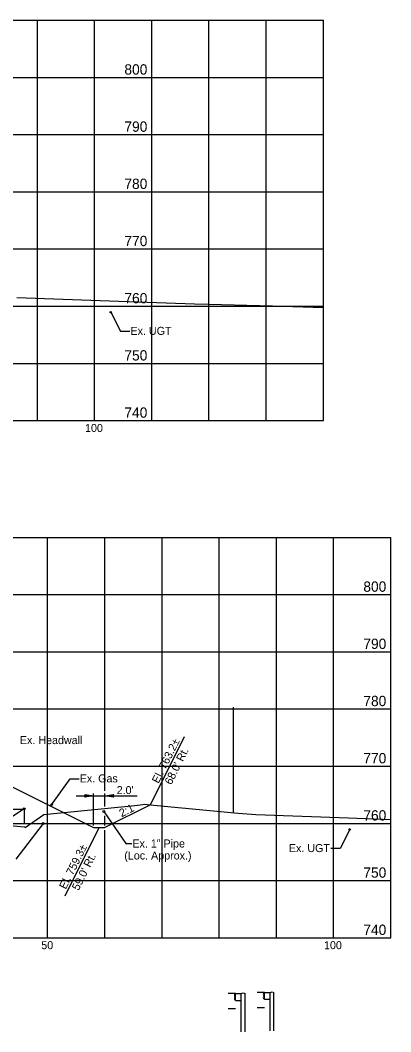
# Model space of a CAD drawing. Extents: x -1395 to 1843, y -1176 to 1887.
# Drawn here: x -168.7 to -39.1, y -802 to -448.3 of the extents above; entities that cross this region are included whole.
import ezdxf

# ---------------------------------------------------------------- set-up
doc = ezdxf.new("R2010")
doc.units = 0
for name, color, linetype in [('DR_X_Storm_Sewer', 7, 'Continuous'), ('GE_X_Alignment', 7, 'Continuous'), ('HY_X_Water_Edge', 7, 'Continuous'), ('PV_X_Shoulder', 7, 'Continuous'), ('RD_X_GR_Lt', 7, 'Continuous'), ('RW_P_Esmt_SH', 7, 'Continuous'), ('RW_P_Esmt_TMP', 7, 'Continuous'), ('RW_X_CL', 7, 'Continuous'), ('SH_Data', 7, 'Continuous'), ('SV_X_Break_Lines', 7, 'Continuous'), ('SV_X_Random_Point', 7, 'Continuous'), ('SV_X_Shot_Marker', 7, 'Continuous'), ('SV_X_Text_Name', 7, 'Continuous')]:
    doc.layers.add(name, color=color, linetype=linetype)

msp = doc.modelspace()

# ---------------------------------------------------------------- linework, layer by layer
at = {"layer": 'DR_X_Storm_Sewer'}
for p, q in [((-221.14, -691.61), (-143.11, -730.62)), ((-123.21, -722.67), (-139.11, -730.62)), ((-143.11, -730.62), (-139.11, -730.62))]:
    msp.add_line(p, q, dxfattribs=at)
at = {"layer": 'GE_X_Alignment'}
for p, q in [((-622.71, -448.27), (-62.71, -448.27)), ((-137.05, -550.37), (-133.64, -557.03)), ((-133.64, -557.03), (-130.45, -557.03)), ((-479.14, -629.14), (-39.14, -629.14)), ((-123.21, -722.67), (-111.28, -698.81)), ((-157.75, -722.6), (-151.31, -713.53)), ((-151.31, -713.53), (-148.11, -713.53)), ((-149.18, -719.49), (-143.11, -719.49)), ((-143.11, -719.49), (-139.11, -719.49)), ((-139.11, -719.49), (-127.8, -719.49)), ((-167.33, -724.03), (-184.69, -735.5)), ((-139.46, -724.99), (-131.75, -736.17)), ((-160.68, -729.2), (-170.3, -741.7)), ((-153.04, -754.48), (-141.11, -730.62)), ((-53.48, -731.25), (-56.88, -737.91)), ((-131.75, -736.17), (-129.69, -736.17)), ((-56.88, -737.91), (-60.08, -737.91)), ((-93.42, -788.69), (-95.99, -788.69)), ((-83.33, -788.34), (-85.89, -788.34)), ((-93.42, -794.03), (-95.99, -794.03)), ((-83.33, -793.67), (-85.89, -793.67))]:
    msp.add_line(p, q, dxfattribs=at)
at = {"layer": 'HY_X_Water_Edge'}
for p, q in [((-169.88, -545.19), (-137.5, -546.35)), ((-137.5, -546.35), (-107.82, -547.45)), ((-107.82, -547.45), (-98.33, -547.65)), ((-98.33, -547.65), (-80.52, -548.18)), ((-80.52, -548.18), (-62.71, -548.7))]:
    msp.add_line(p, q, dxfattribs=at)
msp.add_lwpolyline([(-172.33, -729.83), (-167.25, -730.3), (-167.06, -730.62), (-160.44, -726.08), (-128.7, -722.92), (-125.8, -722.52), (-125.35, -722.47), (-120.89, -722.87), (-92.51, -725.62), (-86.31, -726.07), (-53.93, -727.23), (-39.14, -727.78)], dxfattribs=at)
at = {"layer": 'PV_X_Shoulder'}
msp.add_circle((-157.75, -722.6), 0.25, dxfattribs=at)
at = {"layer": 'RD_X_GR_Lt'}
for centre in [(-137.05, -550.37), (-53.48, -731.25)]:
    msp.add_circle(centre, 0.25, dxfattribs=at)
at = {"layer": 'RW_P_Esmt_SH'}
for p, q in [((-167.18, -724.31), (-177.24, -724.31)), ((-167.18, -729.31), (-167.18, -724.31)), ((-167.18, -729.31), (-170.54, -729.31))]:
    msp.add_line(p, q, dxfattribs=at)
at = {"layer": 'RW_P_Esmt_TMP'}
for p, q in [((-162.71, -588.27), (-162.71, -448.27)), ((-142.71, -588.27), (-142.71, -448.27)), ((-122.71, -588.27), (-122.71, -448.27)), ((-102.71, -588.27), (-102.71, -448.27)), ((-82.71, -588.27), (-82.71, -448.27)), ((-62.71, -588.27), (-62.71, -448.27)), ((-622.71, -468.27), (-62.71, -468.27)), ((-622.71, -488.27), (-62.71, -488.27)), ((-622.71, -508.27), (-62.71, -508.27)), ((-622.71, -528.27), (-62.71, -528.27)), ((-622.71, -548.27), (-62.71, -548.27)), ((-622.71, -568.27), (-62.71, -568.27)), ((-622.71, -588.27), (-62.71, -588.27)), ((-159.14, -769.14), (-159.14, -629.14)), ((-139.14, -717.73), (-139.14, -629.14)), ((-119.14, -769.14), (-119.14, -629.14)), ((-99.14, -769.14), (-99.14, -629.14)), ((-79.14, -769.14), (-79.14, -629.14)), ((-59.14, -769.14), (-59.14, -629.14)), ((-39.14, -769.14), (-39.14, -629.14)), ((-479.14, -649.14), (-39.14, -649.14)), ((-479.14, -669.14), (-39.14, -669.14)), ((-479.14, -689.14), (-39.14, -689.14)), ((-479.14, -709.14), (-39.14, -709.14)), ((-479.14, -729.14), (-39.14, -729.14)), ((-139.14, -769.14), (-139.14, -731.48)), ((-479.14, -749.14), (-39.14, -749.14)), ((-479.14, -769.14), (-39.14, -769.14))]:
    msp.add_line(p, q, dxfattribs=at)
at = {"layer": 'RW_X_CL'}
for p, q in [((-83.46, -788.46), (-83.33, -788.46)), ((-83.33, -790.67), (-83.33, -788.34)), ((-83.33, -788.34), (-81.33, -788.34)), ((-81.33, -788.34), (-80.66, -788.01)), ((-81.33, -801.67), (-81.33, -788.34)), ((-80.66, -788.01), (-79.99, -788.34)), ((-79.99, -801.67), (-79.99, -788.34)), ((-83.46, -790.56), (-83.33, -790.56)), ((-83.33, -790.67), (-81.33, -790.67))]:
    msp.add_line(p, q, dxfattribs=at)
for centre, major_axis, start_param, end_param in [((-83.06, -788.92), (0.667, 0), 2.214297, 4.068888), ((-83.06, -790.09), (0.667, 0), 2.214297, 4.068888), ((-83.46, -789.51), (-0.133, 0), 1.570796, 4.712389)]:
    msp.add_ellipse(centre, major_axis=major_axis, ratio=0.875, start_param=start_param, end_param=end_param, dxfattribs=at)
at = {"layer": 'SV_X_Break_Lines'}
msp.add_line((-94.14, -725.46), (-94.14, -688.55), dxfattribs=at)
at = {"layer": 'SV_X_Random_Point'}
for p, q in [((-143.11, -719.49), (-146.08, -719.98)), ((-146.08, -719.98), (-146.08, -719.98)), ((-146.07, -719), (-146.07, -719)), ((-146.07, -719), (-143.11, -719.49)), ((-143.11, -729.89), (-143.11, -718.7)), ((-139.11, -723.29), (-139.11, -718.7)), ((-139.11, -719.49), (-136.15, -719)), ((-136.16, -719.98), (-139.11, -719.49)), ((-136.16, -719.98), (-136.16, -719.98)), ((-136.15, -719), (-136.15, -719)), ((-139.11, -729.89), (-139.11, -726.46))]:
    msp.add_line(p, q, dxfattribs=at)
for centre, start, end in [((-146.83, -719.48), 326.178, 32.8588), ((-135.4, -719.5), 146.178, 212.8588)]:
    msp.add_arc(centre, 0.9, start, end, dxfattribs=at)
at = {"layer": 'SV_X_Shot_Marker'}
for centre in [(-167.33, -724.03), (-139.46, -724.99), (-160.68, -729.2)]:
    msp.add_circle(centre, 0.333, dxfattribs=at)
at = {"layer": 'SV_X_Text_Name'}
for p, q in [((-93.56, -788.81), (-93.42, -788.81)), ((-93.42, -791.03), (-93.42, -788.69)), ((-93.42, -788.69), (-91.42, -788.69)), ((-91.42, -788.69), (-90.76, -788.36)), ((-91.42, -802.02), (-91.42, -788.69)), ((-90.76, -788.36), (-90.09, -788.69)), ((-90.09, -802.02), (-90.09, -788.69)), ((-93.56, -790.91), (-93.42, -790.91)), ((-93.42, -791.03), (-91.42, -791.03))]:
    msp.add_line(p, q, dxfattribs=at)
for centre, major_axis, start_param, end_param in [((-93.16, -789.28), (0.667, 0), 2.214297, 4.068888), ((-93.16, -790.44), (0.667, 0), 2.214297, 4.068888), ((-93.56, -789.86), (-0.133, 0), 1.570796, 4.712389)]:
    msp.add_ellipse(centre, major_axis=major_axis, ratio=0.875, start_param=start_param, end_param=end_param, dxfattribs=at)

# ---------------------------------------------------------------- texts
at = {"layer": 'SH_Data'}
for s, height, p in [('800', 3.6, (-132.3, -467.27)), ('790', 3.6, (-132.3, -487.27)), ('780', 3.6, (-132.3, -507.27)), ('770', 3.6, (-132.3, -527.27)), ('760', 3.6, (-132.3, -547.27)), ('Ex. UGT', 2.8, (-130.17, -558.3)), ('750', 3.6, (-132.3, -567.27)), ('740', 3.6, (-132.3, -587.27)), ('100', 2.8, (-146.06, -592.27)), ('800', 3.6, (-48.73, -648.14)), ('790', 3.6, (-48.73, -668.14)), ('780', 3.6, (-48.73, -688.14)), ('Ex. Headwall', 2.8, (-168.85, -701.42)), ('770', 3.6, (-48.73, -708.14)), ('Ex. Gas', 2.8, (-147.93, -714.81)), ("2.0'", 2.8, (-135, -718.91)), ('760', 3.6, (-48.73, -728.14)), ('Ex. 1" Pipe', 2.8, (-129.51, -737.58)), ('(Loc. Approx.)', 2.8, (-132.33, -741.78)), ('Ex. UGT', 2.8, (-74.77, -739.18)), ('750', 3.6, (-48.73, -748.14)), ('740', 3.6, (-48.73, -768.14)), ('50', 2.8, (-161.36, -773.14)), ('100', 2.8, (-62.48, -773.14))]:
    msp.add_text(s, height=height, dxfattribs=at).set_placement(p)
for s, rotation, p in [('El. 763.2±', 63.4349, (-120.36, -715.4)), ("68.0' Rt.", 63.4349, (-115.89, -715.86)), ('2:1', 26.5651, (-133.27, -727.03)), ('El. 759.3±', 63.4349, (-152.78, -752.38)), ("59.0' Rt.", 63.4349, (-148.31, -752.84))]:
    msp.add_text(s, height=2.8, rotation=rotation, dxfattribs=at).set_placement(p)

doc.saveas('drawing.dxf')
